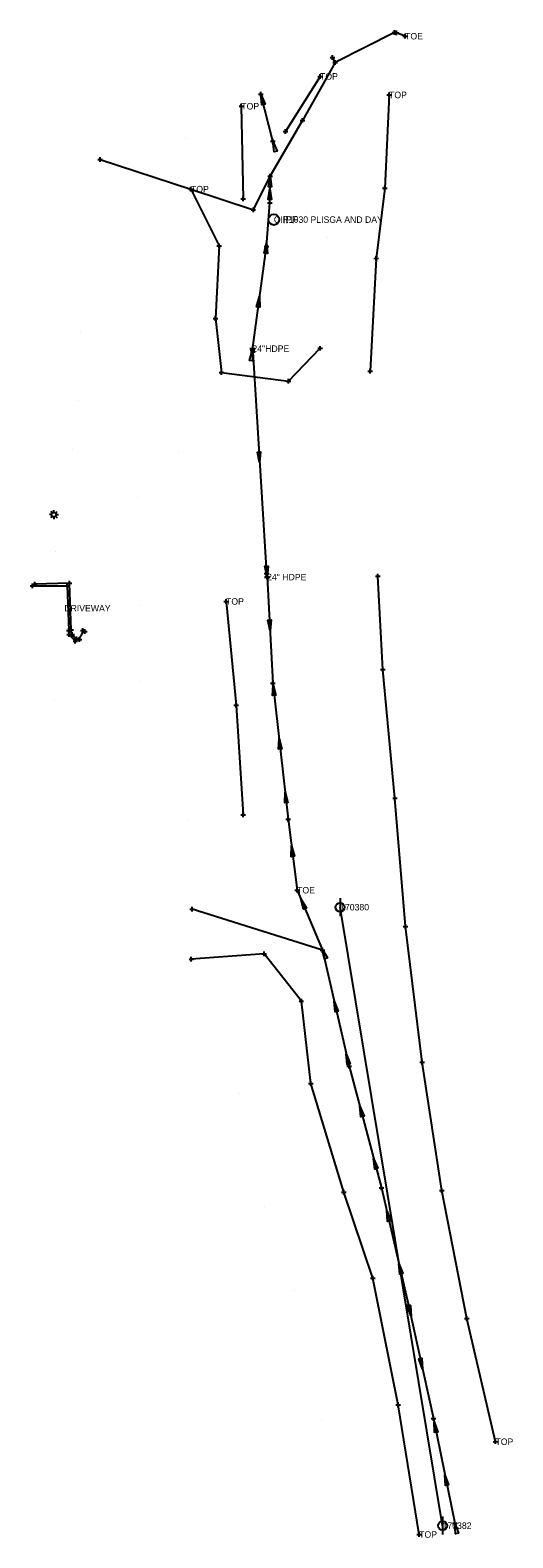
# Model space of a CAD drawing. Extents: x 1733239 to 1734352, y 466612 to 468622.
# Drawn here: x 1733713 to 1733846.8, y 467243.5 to 467661.8 of the extents above; entities that cross this region are included whole.
import ezdxf

# ---------------------------------------------------------------- set-up
doc = ezdxf.new("R2010")
doc.units = 0
for name, color, linetype in [('D_Terrain_Breaklines', 7, 'Continuous'), ('Default', 7, 'Continuous'), ('S_Terrain_Boundary', 7, 'Continuous'), ('S_Terrain_Holes', 7, 'Continuous'), ('S_Terrain_Imported_Contours', 7, 'Continuous'), ('S_Terrain_Islands', 7, 'Continuous'), ('S_Terrain_Major_Contours', 7, 'Continuous'), ('S_Terrain_Major_Contours_Label', 7, 'Continuous'), ('S_Terrain_Minor_Contours', 7, 'Continuous'), ('S_Terrain_Minor_Contours_Label', 7, 'Continuous'), ('S_Terrain_Triangle_Vertices', 7, 'Continuous'), ('S_Terrain_Triangles', 7, 'Continuous'), ('S_Terrain_Voids', 7, 'Continuous'), ('S_Traffic_Sign_SinglePost', 7, 'Continuous'), ('S_Utilities_Pole_StreetLight', 7, 'Continuous')]:
    doc.layers.add(name, color=color, linetype=linetype)

msp = doc.modelspace()

# ---------------------------------------------------------------- linework, layer by layer
at = {"layer": 'D_Terrain_Breaklines'}
for p, q in [((1733723.87, 467508.35), (1733714.33, 467508.06)), ((1733724.35, 467495.39), (1733723.87, 467508.35))]:
    msp.add_line(p, q, dxfattribs=at)
msp.add_lwpolyline([(1733727.59, 467495.2), (1733727.49, 467494.9), (1733727.4, 467494.62), (1733727.3, 467494.36), (1733727.2, 467494.12), (1733727.1, 467493.9), (1733727.01, 467493.7), (1733726.9, 467493.52), (1733726.8, 467493.36), (1733726.7, 467493.23), (1733726.59, 467493.12), (1733726.48, 467493.03), (1733726.36, 467492.96), (1733726.25, 467492.92), (1733726.12, 467492.9), (1733726, 467492.9), (1733725.87, 467492.94), (1733725.65, 467493.04), (1733725.42, 467493.2), (1733725.2, 467493.4), (1733724.99, 467493.63), (1733724.81, 467493.88), (1733724.65, 467494.15), (1733724.52, 467494.44), (1733724.43, 467494.74), (1733724.38, 467495.05), (1733724.35, 467495.39)], dxfattribs=at)
at = {"layer": 'Default'}
for p, q in [((1733774.63, 467573.42), (1733774.63, 467573.42)), ((1733778.71, 467510.04), (1733778.71, 467510.04)), ((1733798.94, 467418.46), (1733798.95, 467418.47)), ((1733798.95, 467418.46), (1733798.94, 467418.47)), ((1733798.95, 467418.46), (1733798.95, 467418.46)), ((1733827.37, 467246.87), (1733827.38, 467246.88)), ((1733827.38, 467246.87), (1733827.37, 467246.88)), ((1733827.37, 467246.88), (1733827.37, 467246.88))]:
    msp.add_line(p, q, dxfattribs=at)
msp.add_lwpolyline([(1733827.37, 467246.88), (1733798.95, 467418.46)], dxfattribs=at)
for centre in [(1733798.95, 467418.46), (1733827.37, 467246.88)]:
    msp.add_circle(centre, 0.00528, dxfattribs=at)
at = {"layer": 'S_Terrain_Boundary'}
for points in [[(1733797.59, 467652.79), (1733788.54, 467636.76)], [(1733779.53, 467621.28), (1733788.54, 467636.76)], [(1733732.41, 467625.91), (1733757.6, 467617.68), (1733774.89, 467611.93), (1733779.53, 467621.28)]]:
    msp.add_lwpolyline(points, dxfattribs=at)
at = {"layer": 'S_Terrain_Holes'}
for points in [[(1733816.97, 467660.11), (1733814.63, 467661.02), (1733814.02, 467661.15), (1733797.59, 467652.79), (1733796.87, 467654.2)], [(1733793.39, 467648.95), (1733783.77, 467633.69)], [(1733771.55, 467640.67), (1733772.09, 467614.96)], [(1733812.53, 467643.81), (1733811.35, 467617.9), (1733808.94, 467598.47), (1733807.32, 467567.19)], [(1733757.6, 467617.68), (1733765.4, 467601.91), (1733764.4, 467581.82), (1733766.03, 467566.77), (1733784.65, 467564.41), (1733793.42, 467573.51)], [(1733842.03, 467270.17), (1733834.07, 467304.32), (1733827.12, 467339.82), (1733821.72, 467375.46), (1733817.06, 467413.12), (1733814.17, 467448.72), (1733810.79, 467484.43), (1733809.42, 467510.29)], [(1733767.32, 467503.29), (1733770.15, 467474.54), (1733772.04, 467444.06)], [(1733787.02, 467423.18), (1733794.07, 467406.51), (1733757.95, 467417.89)], [(1733820.88, 467244.42), (1733815.02, 467280.43), (1733808.03, 467315.58), (1733800.01, 467339.4), (1733790.8, 467369.51), (1733788.2, 467392.42), (1733777.87, 467405.51), (1733757.69, 467404.03)]]:
    msp.add_lwpolyline(points, dxfattribs=at)
at = {"layer": 'S_Terrain_Imported_Contours'}
msp.add_lwpolyline([(1733774.71, 467572.56), (1733778.54, 467511.05)], dxfattribs=at)
at = {"layer": 'S_Terrain_Islands'}
for p, q in [((1733713.64, 467507.58), (1733723.3, 467507.66)), ((1733723.3, 467507.66), (1733723.7, 467495.27)), ((1733723.7, 467495.27), (1733723.84, 467494.14)), ((1733723.84, 467494.14), (1733725.52, 467492.23))]:
    msp.add_line(p, q, dxfattribs=at)
at = {"layer": 'S_Terrain_Major_Contours'}
for p, q in [((1733755.99, 467631.76), (1733755.99, 467631.76)), ((1733789.63, 467611.53), (1733789.63, 467611.53)), ((1733795.45, 467604.35), (1733795.45, 467604.35)), ((1733727.09, 467577.87), (1733727.09, 467577.87)), ((1733726.32, 467559.12), (1733726.32, 467559.12)), ((1733724.71, 467545.38), (1733724.71, 467545.38)), ((1733754.05, 467544.65), (1733754.05, 467544.65)), ((1733742.79, 467532.2), (1733742.79, 467532.2)), ((1733720.04, 467517.2), (1733720.04, 467517.2)), ((1733743.32, 467502.1), (1733743.32, 467502.1)), ((1733743.71, 467481.05), (1733743.71, 467481.05)), ((1733719.88, 467476.04), (1733719.88, 467476.04)), ((1733756.55, 467442.44), (1733756.55, 467442.44)), ((1733771.14, 467366.77), (1733771.14, 467366.77)), ((1733778.09, 467335.44), (1733778.09, 467335.44)), ((1733786.4, 467312.21), (1733786.4, 467312.21)), ((1733793.67, 467275.95), (1733793.67, 467275.95))]:
    msp.add_line(p, q, dxfattribs=at)
at = {"layer": 'S_Terrain_Major_Contours_Label'}
for p, q in [((1733718.95, 467527.37), (1733718.32, 467527.37)), ((1733719.13, 467527.81), (1733718.69, 467528.25)), ((1733719.13, 467526.93), (1733718.69, 467526.49)), ((1733719.57, 467528), (1733719.57, 467528.62)), ((1733720.01, 467527.81), (1733720.45, 467528.25)), ((1733720.01, 467526.93), (1733720.45, 467526.49)), ((1733720.2, 467527.37), (1733720.82, 467527.37)), ((1733719.57, 467526.75), (1733719.57, 467526.12))]:
    msp.add_line(p, q, dxfattribs=at)
msp.add_circle((1733719.57, 467527.37), 0.624, dxfattribs=at)
at = {"layer": 'S_Terrain_Minor_Contours'}
for p, q in [((1733813.38, 467661.15), (1733814.66, 467661.15)), ((1733813.99, 467661.02), (1733815.27, 467661.02)), ((1733814.02, 467660.51), (1733814.02, 467661.78)), ((1733814.02, 467661.15), (1733814.02, 467661.15)), ((1733814.63, 467660.38), (1733814.63, 467661.66)), ((1733814.63, 467661.02), (1733814.63, 467661.02)), ((1733816.97, 467659.48), (1733816.97, 467660.75)), ((1733816.33, 467660.11), (1733817.61, 467660.12)), ((1733816.97, 467660.11), (1733816.97, 467660.11)), ((1733796.23, 467654.2), (1733797.5, 467654.2)), ((1733796.87, 467653.56), (1733796.87, 467654.84)), ((1733796.87, 467654.2), (1733796.87, 467654.2)), ((1733796.95, 467652.79), (1733798.23, 467652.8)), ((1733796.95, 467652.79), (1733798.23, 467652.8)), ((1733797.59, 467652.16), (1733797.59, 467653.43)), ((1733797.59, 467652.16), (1733797.59, 467653.43)), ((1733797.59, 467652.79), (1733797.59, 467652.79)), ((1733797.59, 467652.79), (1733797.59, 467652.79)), ((1733792.75, 467648.95), (1733794.02, 467648.95)), ((1733793.39, 467648.31), (1733793.38, 467649.59)), ((1733793.39, 467648.95), (1733793.39, 467648.95)), ((1733776.32, 467644), (1733777.59, 467644)), ((1733776.96, 467643.37), (1733776.95, 467644.64)), ((1733776.96, 467644), (1733776.96, 467644)), ((1733812.53, 467643.18), (1733812.53, 467644.45)), ((1733770.92, 467640.67), (1733772.19, 467640.68)), ((1733771.56, 467640.04), (1733771.55, 467641.31)), ((1733771.55, 467640.67), (1733771.55, 467640.67)), ((1733811.9, 467643.81), (1733813.17, 467643.82)), ((1733812.53, 467643.81), (1733812.53, 467643.81)), ((1733787.9, 467636.76), (1733789.18, 467636.76)), ((1733788.54, 467636.12), (1733788.54, 467637.4)), ((1733788.54, 467636.76), (1733788.54, 467636.76)), ((1733780.31, 467630.37), (1733780.31, 467631.64)), ((1733783.14, 467633.69), (1733784.41, 467633.69)), ((1733783.77, 467633.05), (1733783.77, 467634.32)), ((1733783.77, 467633.69), (1733783.77, 467633.69)), ((1733779.68, 467631), (1733780.95, 467631)), ((1733780.31, 467631), (1733780.31, 467631)), ((1733731.77, 467625.91), (1733733.04, 467625.91)), ((1733732.41, 467625.27), (1733732.41, 467626.55)), ((1733732.41, 467625.91), (1733732.41, 467625.91)), ((1733778.89, 467621.28), (1733780.16, 467621.28)), ((1733778.89, 467621.28), (1733780.16, 467621.28)), ((1733779.53, 467620.64), (1733779.52, 467621.92)), ((1733779.53, 467620.64), (1733779.52, 467621.92)), ((1733779.53, 467621.28), (1733779.53, 467621.28)), ((1733779.53, 467621.28), (1733779.53, 467621.28)), ((1733756.96, 467617.67), (1733758.23, 467617.68)), ((1733756.96, 467617.67), (1733758.23, 467617.68)), ((1733757.6, 467617.04), (1733757.59, 467618.31)), ((1733757.6, 467617.04), (1733757.59, 467618.31)), ((1733757.6, 467617.68), (1733757.6, 467617.68)), ((1733757.6, 467617.68), (1733757.6, 467617.68)), ((1733771.46, 467614.96), (1733772.73, 467614.96)), ((1733772.09, 467614.32), (1733772.09, 467615.59)), ((1733772.09, 467614.96), (1733772.09, 467614.96)), ((1733810.71, 467617.9), (1733811.98, 467617.9)), ((1733811.35, 467617.26), (1733811.34, 467618.53)), ((1733811.35, 467617.9), (1733811.35, 467617.9)), ((1733774.26, 467611.92), (1733775.53, 467611.93)), ((1733774.89, 467611.29), (1733774.89, 467612.56)), ((1733774.89, 467611.93), (1733774.89, 467611.93)), ((1733778.83, 467613.92), (1733780.11, 467613.92)), ((1733779.47, 467613.28), (1733779.47, 467614.55)), ((1733779.47, 467613.92), (1733779.47, 467613.92)), ((1733765.4, 467601.27), (1733765.4, 467602.55)), ((1733778.5, 467601.14), (1733778.5, 467602.41)), ((1733764.77, 467601.91), (1733766.04, 467601.91)), ((1733765.4, 467601.91), (1733765.4, 467601.91)), ((1733777.86, 467601.77), (1733779.14, 467601.78)), ((1733778.5, 467601.77), (1733778.5, 467601.77)), ((1733808.3, 467598.47), (1733809.58, 467598.48)), ((1733808.94, 467597.84), (1733808.94, 467599.11)), ((1733808.94, 467598.47), (1733808.94, 467598.47)), ((1733763.77, 467581.82), (1733765.04, 467581.82)), ((1733764.4, 467581.18), (1733764.4, 467582.46)), ((1733764.4, 467581.82), (1733764.4, 467581.82)), ((1733773.99, 467573.05), (1733775.27, 467573.05)), ((1733774.63, 467572.42), (1733774.63, 467573.69)), ((1733774.63, 467573.05), (1733774.63, 467573.05)), ((1733774.71, 467571.92), (1733774.71, 467573.2)), ((1733792.79, 467573.51), (1733794.06, 467573.51)), ((1733793.43, 467572.87), (1733793.42, 467574.15)), ((1733793.42, 467573.51), (1733793.42, 467573.51)), ((1733774.08, 467572.56), (1733775.35, 467572.56)), ((1733774.71, 467572.56), (1733774.71, 467572.56)), ((1733765.39, 467566.77), (1733766.66, 467566.77)), ((1733766.03, 467566.13), (1733766.03, 467567.4)), ((1733766.03, 467566.77), (1733766.03, 467566.77)), ((1733784.65, 467563.77), (1733784.65, 467565.04)), ((1733806.68, 467567.19), (1733807.96, 467567.19)), ((1733807.32, 467566.55), (1733807.32, 467567.83)), ((1733807.32, 467567.19), (1733807.32, 467567.19)), ((1733784.02, 467564.41), (1733785.29, 467564.41)), ((1733784.65, 467564.41), (1733784.65, 467564.41)), ((1733777.91, 467511.05), (1733779.18, 467511.05)), ((1733778.06, 467510.13), (1733779.33, 467510.13)), ((1733778.54, 467510.41), (1733778.54, 467511.69)), ((1733778.54, 467511.05), (1733778.54, 467511.05)), ((1733778.7, 467509.49), (1733778.69, 467510.76)), ((1733778.69, 467510.13), (1733778.69, 467510.13)), ((1733808.79, 467510.29), (1733810.06, 467510.29)), ((1733809.42, 467509.65), (1733809.42, 467510.93)), ((1733809.42, 467510.29), (1733809.42, 467510.29)), ((1733713, 467507.58), (1733714.27, 467507.58)), ((1733713.64, 467506.95), (1733713.63, 467508.22)), ((1733713.64, 467507.58), (1733713.64, 467507.58)), ((1733713.69, 467508.06), (1733714.96, 467508.07)), ((1733714.33, 467507.43), (1733714.33, 467508.7)), ((1733714.33, 467508.06), (1733714.33, 467508.06)), ((1733722.67, 467507.66), (1733723.94, 467507.67)), ((1733723.23, 467508.35), (1733724.51, 467508.35)), ((1733723.31, 467507.03), (1733723.3, 467508.3)), ((1733723.3, 467507.66), (1733723.3, 467507.66)), ((1733723.87, 467507.72), (1733723.87, 467508.99)), ((1733723.87, 467508.35), (1733723.87, 467508.35)), ((1733766.68, 467503.29), (1733767.95, 467503.29)), ((1733767.32, 467502.65), (1733767.32, 467503.93)), ((1733767.32, 467503.29), (1733767.32, 467503.29)), ((1733723.06, 467495.26), (1733724.34, 467495.27)), ((1733723.21, 467494.14), (1733724.48, 467494.14)), ((1733723.7, 467494.63), (1733723.7, 467495.9)), ((1733723.7, 467495.27), (1733723.7, 467495.27)), ((1733723.71, 467495.38), (1733724.99, 467495.39)), ((1733723.84, 467493.5), (1733723.84, 467494.78)), ((1733723.84, 467494.14), (1733723.84, 467494.14)), ((1733724.01, 467494.14), (1733725.29, 467494.15)), ((1733724.35, 467494.75), (1733724.35, 467496.02)), ((1733724.35, 467495.39), (1733724.35, 467495.39)), ((1733724.65, 467493.51), (1733724.65, 467494.78)), ((1733724.65, 467494.15), (1733724.65, 467494.15)), ((1733725.87, 467492.3), (1733725.86, 467493.57)), ((1733726.67, 467492.07), (1733726.67, 467493.35)), ((1733726.95, 467495.2), (1733728.22, 467495.2)), ((1733727.52, 467494.97), (1733728.8, 467494.97)), ((1733727.59, 467494.56), (1733727.59, 467495.84)), ((1733727.59, 467495.2), (1733727.59, 467495.2)), ((1733728.16, 467494.34), (1733728.16, 467495.61)), ((1733728.16, 467494.97), (1733728.16, 467494.97)), ((1733724.88, 467492.23), (1733726.15, 467492.23)), ((1733725.23, 467492.94), (1733726.5, 467492.94)), ((1733725.52, 467491.59), (1733725.52, 467492.86)), ((1733725.52, 467492.23), (1733725.52, 467492.23)), ((1733725.87, 467492.94), (1733725.87, 467492.94)), ((1733726.03, 467492.71), (1733727.31, 467492.71)), ((1733726.67, 467492.71), (1733726.67, 467492.71)), ((1733810.79, 467483.8), (1733810.79, 467485.07)), ((1733780.29, 467479.98), (1733780.29, 467481.26)), ((1733810.16, 467484.43), (1733811.43, 467484.43)), ((1733810.79, 467484.43), (1733810.79, 467484.43)), ((1733779.66, 467480.62), (1733780.93, 467480.62)), ((1733780.29, 467480.62), (1733780.29, 467480.62)), ((1733769.51, 467474.54), (1733770.79, 467474.54)), ((1733770.15, 467473.9), (1733770.15, 467475.17)), ((1733770.15, 467474.54), (1733770.15, 467474.54)), ((1733813.53, 467448.72), (1733814.8, 467448.72)), ((1733814.17, 467448.08), (1733814.17, 467449.35)), ((1733814.17, 467448.72), (1733814.17, 467448.72)), ((1733771.41, 467444.06), (1733772.68, 467444.06)), ((1733772.05, 467443.42), (1733772.04, 467444.7)), ((1733772.04, 467444.06), (1733772.04, 467444.06)), ((1733784.54, 467442.23), (1733784.54, 467443.5)), ((1733783.91, 467442.87), (1733785.18, 467442.87)), ((1733784.54, 467442.87), (1733784.54, 467442.87)), ((1733786.39, 467423.17), (1733787.66, 467423.18)), ((1733786.39, 467423.17), (1733787.66, 467423.18)), ((1733787.02, 467422.54), (1733787.02, 467423.81)), ((1733787.02, 467422.54), (1733787.02, 467423.81)), ((1733787.02, 467423.18), (1733787.02, 467423.18)), ((1733787.02, 467423.18), (1733787.02, 467423.18)), ((1733757.95, 467417.25), (1733757.95, 467418.53)), ((1733757.32, 467417.89), (1733758.59, 467417.89)), ((1733757.95, 467417.89), (1733757.95, 467417.89)), ((1733816.42, 467413.12), (1733817.69, 467413.12)), ((1733817.06, 467412.48), (1733817.06, 467413.75)), ((1733817.06, 467413.12), (1733817.06, 467413.12)), ((1733777.23, 467405.51), (1733778.51, 467405.51)), ((1733777.87, 467404.87), (1733777.87, 467406.15)), ((1733777.87, 467405.51), (1733777.87, 467405.51)), ((1733793.44, 467406.51), (1733794.71, 467406.51)), ((1733793.44, 467406.51), (1733794.71, 467406.51)), ((1733794.07, 467405.87), (1733794.07, 467407.15)), ((1733794.07, 467405.87), (1733794.07, 467407.15)), ((1733794.07, 467406.51), (1733794.07, 467406.51)), ((1733794.07, 467406.51), (1733794.07, 467406.51)), ((1733757.05, 467404.03), (1733758.32, 467404.03)), ((1733757.69, 467403.4), (1733757.69, 467404.67)), ((1733757.69, 467404.03), (1733757.69, 467404.03)), ((1733788.2, 467391.79), (1733788.2, 467393.06)), ((1733787.57, 467392.42), (1733788.84, 467392.42)), ((1733788.2, 467392.42), (1733788.2, 467392.42)), ((1733800.83, 467374.33), (1733802.1, 467374.33)), ((1733801.47, 467373.69), (1733801.46, 467374.97)), ((1733801.47, 467374.33), (1733801.47, 467374.33)), ((1733821.08, 467375.45), (1733822.36, 467375.46)), ((1733821.72, 467374.82), (1733821.72, 467376.09)), ((1733821.72, 467375.46), (1733821.72, 467375.46)), ((1733790.17, 467369.51), (1733791.44, 467369.52)), ((1733790.8, 467368.88), (1733790.8, 467370.15)), ((1733790.8, 467369.51), (1733790.8, 467369.51)), ((1733799.37, 467339.4), (1733800.64, 467339.4)), ((1733800.01, 467338.76), (1733800.01, 467340.04)), ((1733800.01, 467339.4), (1733800.01, 467339.4)), ((1733809.76, 467340.56), (1733811.03, 467340.57)), ((1733810.4, 467339.93), (1733810.39, 467341.2)), ((1733810.4, 467340.57), (1733810.4, 467340.57)), ((1733826.49, 467339.82), (1733827.76, 467339.82)), ((1733827.13, 467339.18), (1733827.12, 467340.46)), ((1733827.12, 467339.82), (1733827.12, 467339.82)), ((1733807.4, 467315.58), (1733808.67, 467315.58)), ((1733808.03, 467314.95), (1733808.03, 467316.22)), ((1733808.03, 467315.58), (1733808.03, 467315.58)), ((1733817.33, 467308.08), (1733818.6, 467308.08)), ((1733817.97, 467307.44), (1733817.96, 467308.71)), ((1733817.96, 467308.08), (1733817.96, 467308.08)), ((1733833.43, 467304.31), (1733834.71, 467304.32)), ((1733834.07, 467303.68), (1733834.07, 467304.95)), ((1733834.07, 467304.32), (1733834.07, 467304.32)), ((1733814.39, 467280.43), (1733815.66, 467280.43)), ((1733815.03, 467279.79), (1733815.02, 467281.06)), ((1733815.02, 467280.43), (1733815.02, 467280.43)), ((1733824.18, 467276.57), (1733825.45, 467276.57)), ((1733824.81, 467275.94), (1733824.81, 467277.21)), ((1733824.81, 467276.57), (1733824.81, 467276.57)), ((1733841.39, 467270.17), (1733842.66, 467270.18)), ((1733842.03, 467269.54), (1733842.03, 467270.81)), ((1733842.03, 467270.17), (1733842.03, 467270.17)), ((1733830.13, 467247.56), (1733831.4, 467247.56)), ((1733830.77, 467246.93), (1733830.77, 467248.2)), ((1733830.77, 467247.56), (1733830.77, 467247.56)), ((1733820.24, 467244.42), (1733821.52, 467244.42)), ((1733820.88, 467243.78), (1733820.88, 467245.05)), ((1733820.88, 467244.42), (1733820.88, 467244.42))]:
    msp.add_line(p, q, dxfattribs=at)
at = {"layer": 'S_Terrain_Minor_Contours_Label'}
for p, q in [((1733773.88, 467573.42), (1733775.38, 467573.42)), ((1733774.63, 467574.17), (1733774.63, 467572.67)), ((1733777.96, 467510.04), (1733779.46, 467510.04)), ((1733778.71, 467510.79), (1733778.71, 467509.29))]:
    msp.add_line(p, q, dxfattribs=at)
at = {"layer": 'S_Terrain_Triangle_Vertices'}
for p, q in [((1733798.95, 467420.96), (1733798.95, 467415.97)), ((1733827.37, 467249.37), (1733827.37, 467244.38))]:
    msp.add_line(p, q, dxfattribs=at)
for centre in [(1733798.95, 467418.46), (1733827.37, 467246.88)]:
    msp.add_circle(centre, 1.25, dxfattribs=at)
at = {"layer": 'S_Terrain_Triangles'}
msp.add_circle((1733780.57, 467609.22), 1.5, dxfattribs=at)
at = {"layer": 'S_Terrain_Voids'}
for p, q in [((1733776.96, 467644), (1733776.96, 467644)), ((1733780.31, 467631), (1733780.31, 467631)), ((1733779.53, 467621.28), (1733779.53, 467621.28)), ((1733779.5, 467617.73), (1733779.5, 467617.73)), ((1733778.58, 467602.79), (1733778.58, 467602.79)), ((1733776.63, 467587.92), (1733776.63, 467587.92)), ((1733774.63, 467573.05), (1733774.63, 467573.05)), ((1733778.69, 467510.13), (1733778.69, 467510.13)), ((1733779.51, 467495.15), (1733779.51, 467495.15)), ((1733780.34, 467480.17), (1733780.34, 467480.17)), ((1733782.02, 467465.27), (1733782.02, 467465.27)), ((1733783.7, 467450.36), (1733783.7, 467450.36)), ((1733785.47, 467435.47), (1733785.47, 467435.47)), ((1733788.04, 467420.78), (1733788.04, 467420.78)), ((1733793.88, 467406.97), (1733793.88, 467406.97)), ((1733797.32, 467392.39), (1733797.32, 467392.39)), ((1733800.67, 467377.78), (1733800.67, 467377.78)), ((1733804.39, 467363.26), (1733804.39, 467363.26)), ((1733808.23, 467348.76), (1733808.23, 467348.76)), ((1733811.88, 467334.21), (1733811.88, 467334.21)), ((1733815.28, 467319.6), (1733815.28, 467319.6)), ((1733818.64, 467304.99), (1733818.64, 467304.99)), ((1733821.82, 467290.33), (1733821.82, 467290.33)), ((1733825, 467275.67), (1733825, 467275.67)), ((1733828.01, 467260.98), (1733828.01, 467260.98)), ((1733830.77, 467247.56), (1733830.77, 467247.56))]:
    msp.add_line(p, q, dxfattribs=at)
for points in [[(1733780.31, 467631), (1733776.96, 467644)], [(1733774.63, 467573.05), (1733778.5, 467601.77), (1733779.47, 467613.92), (1733779.53, 467621.28)], [(1733778.69, 467510.13), (1733780.29, 467480.62), (1733784.54, 467442.87), (1733787.02, 467423.18), (1733794.07, 467406.51), (1733801.47, 467374.33), (1733810.4, 467340.57), (1733817.96, 467308.08), (1733824.81, 467276.57), (1733830.77, 467247.56)]]:
    msp.add_lwpolyline(points, dxfattribs=at)
for points in [[(1733776.96, 467644), (1733778.13, 467641.24), (1733777.27, 467641.02)], [(1733780.31, 467631), (1733781.49, 467628.24), (1733780.62, 467628.02)], [(1733779.53, 467621.28), (1733779.95, 467618.31), (1733779.06, 467618.32)], [(1733779.5, 467617.73), (1733779.92, 467614.76), (1733779.03, 467614.76)], [(1733778.58, 467602.79), (1733778.79, 467599.8), (1733777.9, 467599.87)], [(1733776.63, 467587.92), (1733776.68, 467584.92), (1733775.79, 467585.04)], [(1733774.63, 467573.05), (1733774.67, 467570.05), (1733773.79, 467570.17)], [(1733778.69, 467510.13), (1733778.09, 467513.07), (1733778.98, 467513.11)], [(1733779.51, 467495.15), (1733778.9, 467498.09), (1733779.79, 467498.14)], [(1733780.34, 467480.17), (1733781.12, 467477.28), (1733780.23, 467477.18)], [(1733782.02, 467465.27), (1733782.79, 467462.37), (1733781.91, 467462.27)], [(1733783.7, 467450.36), (1733784.47, 467447.47), (1733783.59, 467447.37)], [(1733785.47, 467435.47), (1733786.29, 467432.58), (1733785.4, 467432.47)], [(1733788.04, 467420.78), (1733789.6, 467418.22), (1733788.78, 467417.87)], [(1733793.88, 467406.97), (1733795.44, 467404.41), (1733794.62, 467404.06)], [(1733797.32, 467392.39), (1733798.41, 467389.6), (1733797.55, 467389.4)], [(1733800.67, 467377.78), (1733801.77, 467374.99), (1733800.9, 467374.79)], [(1733804.39, 467363.26), (1733805.58, 467360.5), (1733804.72, 467360.28)], [(1733808.23, 467348.76), (1733809.42, 467346.01), (1733808.56, 467345.78)], [(1733811.88, 467334.21), (1733812.98, 467331.42), (1733812.12, 467331.22)], [(1733815.28, 467319.6), (1733816.39, 467316.82), (1733815.52, 467316.61)], [(1733818.64, 467304.99), (1733817.57, 467307.79), (1733818.44, 467307.98)], [(1733821.82, 467290.33), (1733820.76, 467293.13), (1733821.63, 467293.32)], [(1733825, 467275.67), (1733826.03, 467272.85), (1733825.16, 467272.68)], [(1733828.01, 467260.98), (1733829.04, 467258.16), (1733828.17, 467257.98)], [(1733830.77, 467247.56), (1733831.8, 467244.75), (1733830.93, 467244.57)]]:
    msp.add_lwpolyline(points, close=True, dxfattribs=at)
at = {"layer": 'S_Utilities_Pole_StreetLight'}
msp.add_line((1733776.63, 467541.8), (1733776.63, 467541.8), dxfattribs=at)
msp.add_lwpolyline([(1733776.63, 467541.8), (1733776, 467544.74), (1733776.89, 467544.79)], close=True, dxfattribs=at)

# ---------------------------------------------------------------- texts
at = {"layer": 'S_Terrain_Triangles'}
msp.add_text('IPF', height=1.996, dxfattribs=at).set_placement((1733783.07, 467608.23))
at = {"layer": 'S_Traffic_Sign_SinglePost'}
for s, p in [('TOE', (1733816.97, 467659.21)), ('TOP', (1733793.39, 467648.05)), ('TOP', (1733812.53, 467642.91)), ('TOP', (1733771.55, 467639.77)), ('TOP', (1733757.6, 467616.78)), ('TOP', (1733757.6, 467616.78)), ('CIR1030 PLISGA AND DAY', (1733780.57, 467608.32)), ('24"HDPE', (1733774.63, 467572.52)), ('24" HDPE', (1733778.71, 467509.14)), ('DRIVEWAY', (1733722.47, 467500.5)), ('TOP', (1733767.32, 467502.39)), ('TOE', (1733787.02, 467422.28)), ('TOE', (1733787.02, 467422.28)), ('170380', (1733798.95, 467417.56)), ('170380', (1733798.95, 467417.56)), ('TOP', (1733842.03, 467269.27)), ('170382', (1733827.37, 467245.98)), ('170382', (1733827.37, 467245.98)), ('TOP', (1733820.88, 467243.52))]:
    msp.add_text(s, height=1.8, dxfattribs=at).set_placement(p)

doc.saveas('drawing.dxf')
